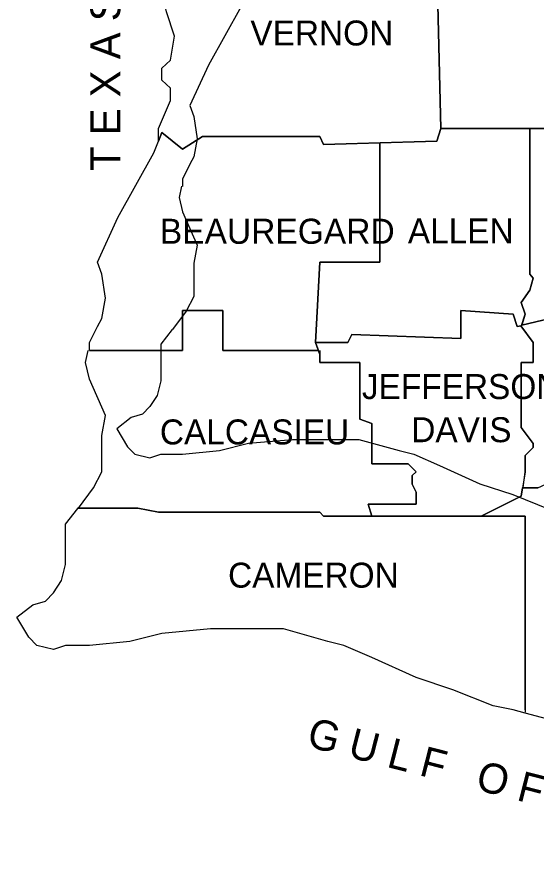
# Model space of a CAD drawing. Extents: x 0.19 to 2.82, y 0.04 to 1.79.
# Drawn here: x 2.2023 to 2.3093, y 1.3862 to 1.5609 of the extents above; entities that cross this region are included whole.
import ezdxf

# ---------------------------------------------------------------- set-up
doc = ezdxf.new("R2010")
doc.units = 0
doc.layers.add('Dist07', color=7, linetype='Continuous')
doc.layers.add('Standard Info', color=7, linetype='Continuous')

msp = doc.modelspace()

# ---------------------------------------------------------------- linework, layer by layer
at = {"layer": 'Dist07'}
msp.add_line((2.23649, 1.5275), (2.23649, 1.526), dxfattribs=at)
for points in [[(2.24857, 1.56308), (2.24182, 1.551), (2.23799, 1.54267), (2.23882, 1.54042), (2.23949, 1.53583), (2.23882, 1.53208), (2.23799, 1.53058), (2.23649, 1.5275), (2.23649, 1.52742)], [(2.23624, 1.52608), (2.23574, 1.52375), (2.23649, 1.52075), (2.23949, 1.51392), (2.23882, 1.51017), (2.23882, 1.50333), (2.23724, 1.50033), (2.2344, 1.4965)], [(2.23432, 1.4965), (2.23199, 1.4935)], [(2.23199, 1.4935), (2.23199, 1.49275), (2.23199, 1.489), (2.23199, 1.4875), (2.23199, 1.48592), (2.23124, 1.48292), (2.22974, 1.48067), (2.22824, 1.47908), (2.2259, 1.47842), (2.2229, 1.47608), (2.22515, 1.47233), (2.22665, 1.47083), (2.22974, 1.47008), (2.23199, 1.47083), (2.23649, 1.47083), (2.24407, 1.47158), (2.25007, 1.47308), (2.25915, 1.47383), (2.26824, 1.47383), (2.27282, 1.47383), (2.28115, 1.47158), (2.28415, 1.47083), (2.2894, 1.4685), (2.29774, 1.46475), (2.30457, 1.4625), (2.31215, 1.45942)]]:
    msp.add_lwpolyline(points, dxfattribs=at)
at = {"layer": 'Standard Info'}
for p, q in [((2.21728, 1.49218), (2.21728, 1.49383)), ((2.30656, 1.46386), (2.30665, 1.46386))]:
    msp.add_line(p, q, dxfattribs=at)
for points in [[(2.27888, 1.57926), (2.27888, 1.57789), (2.28548, 1.57789), (2.28548, 1.57202), (2.28887, 1.57202), (2.2897, 1.53792)], [(2.27888, 1.57926), (2.27888, 1.57789), (2.28548, 1.57789), (2.28548, 1.57202), (2.28887, 1.57202), (2.2897, 1.53792)], [(2.2897, 1.53792), (2.28887, 1.57202), (2.28548, 1.57202), (2.28548, 1.57789), (2.27888, 1.57789), (2.27888, 1.57926)], [(2.27888, 1.57917), (2.27888, 1.57789), (2.28548, 1.57789), (2.28548, 1.57202), (2.28887, 1.57202), (2.2897, 1.53792)], [(2.23149, 1.53536), (2.23149, 1.53792), (2.23396, 1.5437), (2.23396, 1.54626), (2.23222, 1.54791), (2.23222, 1.55039), (2.23396, 1.55204), (2.23479, 1.55699), (2.23314, 1.56203), (2.23222, 1.56625), (2.23176, 1.5668)], [(2.33379, 1.5437), (2.33131, 1.5437), (2.32875, 1.5437), (2.32627, 1.54461), (2.32545, 1.54709), (2.32462, 1.54709), (2.32297, 1.54626), (2.32215, 1.54461), (2.3204, 1.54287), (2.31793, 1.54122), (2.31628, 1.53792), (2.2897, 1.53792)], [(2.30803, 1.53792), (2.31628, 1.53792), (2.31793, 1.54122), (2.3204, 1.54287), (2.32215, 1.54461), (2.32297, 1.54626), (2.32462, 1.54709), (2.32545, 1.54709), (2.32627, 1.54461), (2.32875, 1.5437), (2.33131, 1.5437), (2.33379, 1.5437), (2.33379, 1.54122), (2.33544, 1.53957), (2.33709, 1.53792), (2.33709, 1.53297), (2.33874, 1.53297)], [(2.2897, 1.53792), (2.28887, 1.53536), (2.2655, 1.53462), (2.26476, 1.53627), (2.24056, 1.53627), (2.23644, 1.53371), (2.23222, 1.5371), (2.23149, 1.53536)], [(2.23149, 1.53536), (2.23222, 1.5371), (2.23644, 1.53371), (2.24056, 1.53627), (2.26476, 1.53627), (2.2655, 1.53462), (2.27714, 1.53499)], [(2.27714, 1.53499), (2.28887, 1.53536), (2.2897, 1.53792)], [(2.2897, 1.53792), (2.30803, 1.53792)], [(2.30629, 1.49713), (2.30711, 1.4997), (2.30629, 1.50208), (2.30803, 1.50465), (2.30876, 1.50712), (2.30803, 1.50795), (2.30803, 1.53792)], [(2.30803, 1.53792), (2.30803, 1.50795), (2.30876, 1.50712), (2.30803, 1.50465), (2.30629, 1.50208), (2.30711, 1.4997), (2.30638, 1.49741)], [(2.23057, 1.53297), (2.23149, 1.53536)], [(2.26385, 1.49383), (2.26476, 1.51042), (2.27714, 1.51042), (2.27714, 1.53499)], [(2.27714, 1.53499), (2.27714, 1.51042), (2.26476, 1.51042), (2.26385, 1.49383), (2.26449, 1.49218)], [(2.21728, 1.49365), (2.21728, 1.49383), (2.21893, 1.49713), (2.21985, 1.49878), (2.22058, 1.503), (2.21985, 1.50795), (2.21893, 1.51042), (2.22315, 1.51959), (2.23057, 1.53297)], [(2.26449, 1.49218), (2.24478, 1.49218), (2.24478, 1.50043), (2.23644, 1.50043), (2.23644, 1.49218), (2.21728, 1.49218)], [(2.21728, 1.49218), (2.23644, 1.49218), (2.23644, 1.50043), (2.24478, 1.50043), (2.24478, 1.49218), (2.26449, 1.49218)], [(2.30629, 1.49731), (2.30546, 1.49713), (2.30464, 1.4997), (2.29382, 1.50043), (2.29382, 1.49466), (2.27136, 1.49548), (2.27054, 1.49383), (2.26385, 1.49383)], [(2.26385, 1.49383), (2.27054, 1.49383), (2.27136, 1.49548), (2.29382, 1.49466), (2.29382, 1.50043), (2.30464, 1.4997), (2.30546, 1.49713), (2.30629, 1.49731)], [(2.3171, 1.49878), (2.31215, 1.49878), (2.30638, 1.49741)], [(2.30638, 1.49741), (2.31215, 1.49878), (2.31793, 1.49878), (2.33626, 1.49878), (2.33626, 1.49466), (2.3413, 1.49466), (2.3413, 1.48714), (2.34543, 1.48384), (2.3446, 1.48219)], [(2.3062, 1.49731), (2.30876, 1.49383), (2.30876, 1.49218), (2.30876, 1.48971), (2.30629, 1.48971), (2.30629, 1.47632), (2.30876, 1.47302), (2.30876, 1.4722), (2.30711, 1.47055), (2.30711, 1.46716), (2.30629, 1.46221), (2.29804, 1.45808)], [(2.30665, 1.46386), (2.30711, 1.46716), (2.30711, 1.47055), (2.30876, 1.4722), (2.30876, 1.47302), (2.30629, 1.47632), (2.30629, 1.48971), (2.30876, 1.48971), (2.30876, 1.49218), (2.30876, 1.49383), (2.3062, 1.49731)], [(2.26476, 1.48971), (2.26476, 1.49136), (2.26385, 1.49383)], [(2.21499, 1.45973), (2.2181, 1.46386), (2.21985, 1.46716), (2.21985, 1.47467), (2.22058, 1.4788), (2.21728, 1.48631), (2.21645, 1.48971), (2.217, 1.49218)], [(2.26476, 1.49218), (2.26476, 1.48971)], [(2.27549, 1.45808), (2.27475, 1.46056), (2.28465, 1.46056), (2.28465, 1.46303), (2.28383, 1.46468), (2.28383, 1.46642), (2.28465, 1.46716), (2.283, 1.46881), (2.27549, 1.46881), (2.27549, 1.47715), (2.27301, 1.47806), (2.27301, 1.48971), (2.26476, 1.48971)], [(2.26476, 1.48971), (2.27301, 1.48971), (2.27301, 1.47806), (2.27549, 1.47715), (2.27549, 1.46881), (2.283, 1.46881), (2.28465, 1.46716), (2.28383, 1.46642), (2.28383, 1.46468), (2.28465, 1.46303), (2.28465, 1.46056), (2.27475, 1.46056), (2.27549, 1.45808)], [(2.30656, 1.46386), (2.30968, 1.46386), (2.31133, 1.46468), (2.3138, 1.46303), (2.31463, 1.46303), (2.31545, 1.46221), (2.31793, 1.46056), (2.31967, 1.45973), (2.32215, 1.45973), (2.3238, 1.45973), (2.32627, 1.46138), (2.3271, 1.46221), (2.32792, 1.46303), (2.32957, 1.46551), (2.33131, 1.46716), (2.33296, 1.46807)], [(2.30711, 1.41811), (2.30711, 1.45808), (2.29804, 1.45808), (2.30629, 1.46221), (2.30656, 1.46386)], [(2.30968, 1.46386), (2.30656, 1.46386)], [(2.21233, 1.45643), (2.2149, 1.45964)], [(2.27549, 1.45808), (2.2655, 1.45808), (2.26476, 1.45891), (2.23149, 1.45891), (2.22727, 1.45973), (2.2148, 1.45973)], [(2.2148, 1.45973), (2.22727, 1.45973), (2.23149, 1.45891), (2.26476, 1.45891), (2.2655, 1.45808), (2.29804, 1.45808)], [(2.29804, 1.45808), (2.27549, 1.45808)], [(2.29804, 1.45808), (2.30711, 1.45808), (2.30711, 1.41766)], [(2.30711, 1.41747), (2.30464, 1.41811), (2.30051, 1.41894), (2.29217, 1.42224), (2.28465, 1.42481), (2.27549, 1.42893), (2.26971, 1.43141), (2.26641, 1.43223), (2.25725, 1.4348), (2.2522, 1.4348), (2.24221, 1.4348), (2.23222, 1.43388), (2.22562, 1.43223), (2.21728, 1.43141), (2.21233, 1.43141), (2.20985, 1.43058), (2.20646, 1.43141), (2.20481, 1.43315), (2.20234, 1.43727), (2.20564, 1.43975), (2.2082, 1.44057), (2.20985, 1.44222), (2.2115, 1.44479), (2.21233, 1.44809), (2.21233, 1.44974), (2.21233, 1.45139), (2.21233, 1.45551), (2.21233, 1.45643)], [(2.33956, 1.41564), (2.33874, 1.41564), (2.33296, 1.41399), (2.33131, 1.41399), (2.32297, 1.41646), (2.3138, 1.41564), (2.30711, 1.41747)]]:
    msp.add_lwpolyline(points, dxfattribs=at)

# ---------------------------------------------------------------- texts
for s, rotation, p in [('T E X A S', 90, (2.22366, 1.52919)), ('G U L F   O F   M E X I C O', 345.6507, (2.26182, 1.41065))]:
    msp.add_text(s, height=0.0062, rotation=rotation, dxfattribs=at).set_placement(p)
for s, height, p in [('VERNON', 0.005147, (2.25045, 1.55506)), ('BEAUREGARD', 0.00517, (2.23179, 1.51419)), ('ALLEN', 0.005147, (2.28291, 1.51427)), ('JEFFERSON', 0.005147, (2.27344, 1.48219)), ('CALCASIEU', 0.005147, (2.2318, 1.47284)), ('DAVIS', 0.005147, (2.28362, 1.4733)), ('CAMERON', 0.005147, (2.24585, 1.44332))]:
    msp.add_text(s, height=height, dxfattribs=at).set_placement(p)

doc.saveas('drawing.dxf')
